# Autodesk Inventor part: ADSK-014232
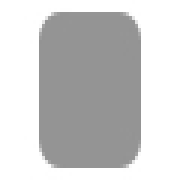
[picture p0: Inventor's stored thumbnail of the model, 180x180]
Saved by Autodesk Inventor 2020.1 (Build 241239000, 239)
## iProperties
Created: 2019-01
Part Number: ADSK-014232
Material: Stahl, weich
Document SubType Name: Modeling
Designer: lutzd
Language: de-DE
Size Designation: 5 x 39,384472 x 39,384472
Categories: <MemberInstance><Categories><Category DisplayName="Sonstige Bauteile" InternalName="5aa15e00-363f-49f2-933f-16f664388e3f" Mnemonic="OTHER"><Category DisplayName
Mass: 60.0398 g
Surface Area: 38.0412 cm^2
Volume: 7.64838 cm^3
Density: 7.85 g/cm^3
Appearance: Halbpoliert
IsCustomPart: 1
Title: Endcap
Author: lutzd
Revision Number: -
Dimensions: 39,4x39,4x5 mm
Mass: 0,06 kg
DocNumber: ADSK-014232
Folder: 01 - Themengebiete\Simplification\01 - Packaging machine\ADSK-014200\Frame\
VDS_Category: 3D Komponenten
VDS_NumSchm: Autodesk
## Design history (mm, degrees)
sketch "Sketch1"
  geometry: L1 (0, 20.175)-(0, -21.446); L2 (-20.203, 0)-(20.169, 0); L3 (-19.692, 19.692)-(19.692, 19.692); L4 (19.692, 19.692)-(19.692, -19.692); L5 (19.692, -19.692)-(-19.692, -19.692); L6 (-19.692, -19.692)-(-19.692, 19.692); 1 further point
  constraints: 12 end point, 2 horizontal, 2 parallel, 2 point on line, 1 perpendicular, 1 vertical
  dimensions: "d0" = 39.38447 distance between parallel lines of L5 L3 (= height); "d1" = 19.69224 distance between parallel lines of L2 L3 (= 0.5 x height); "d2" = 39.38447 distance between parallel lines of L6 L4 (= width); "d3" = 19.69224 distance between parallel lines of L6 L1 (= 0.5 x width)
extrude "Extrusion1" new body sketch "Sketch1" distance "d4" = 5 (= thickness); taper "d5" = 0 deg
fillet "Fillet1" dims "d6" = 5 (= fillet), "d7" = 0, "fillet" = 5 [user parameter; used in 1 equation term]
chamfer "Chamfer1" distance "d8" = 0 (computed from chamfer); stored, may be unused: second distance "d9" = 2, angle "d10" = 45 deg; dims "d11" = 0, "chamfer" = 0 [user parameter; used in 1 equation term]
body "Solid1"
other parameters: "thickness" = 5 [user parameter; used in 1 equation term], "width" = 39.38447 [user parameter; used in 2 equation terms], "height" = 39.38447 [user parameter; used in 2 equation terms]
